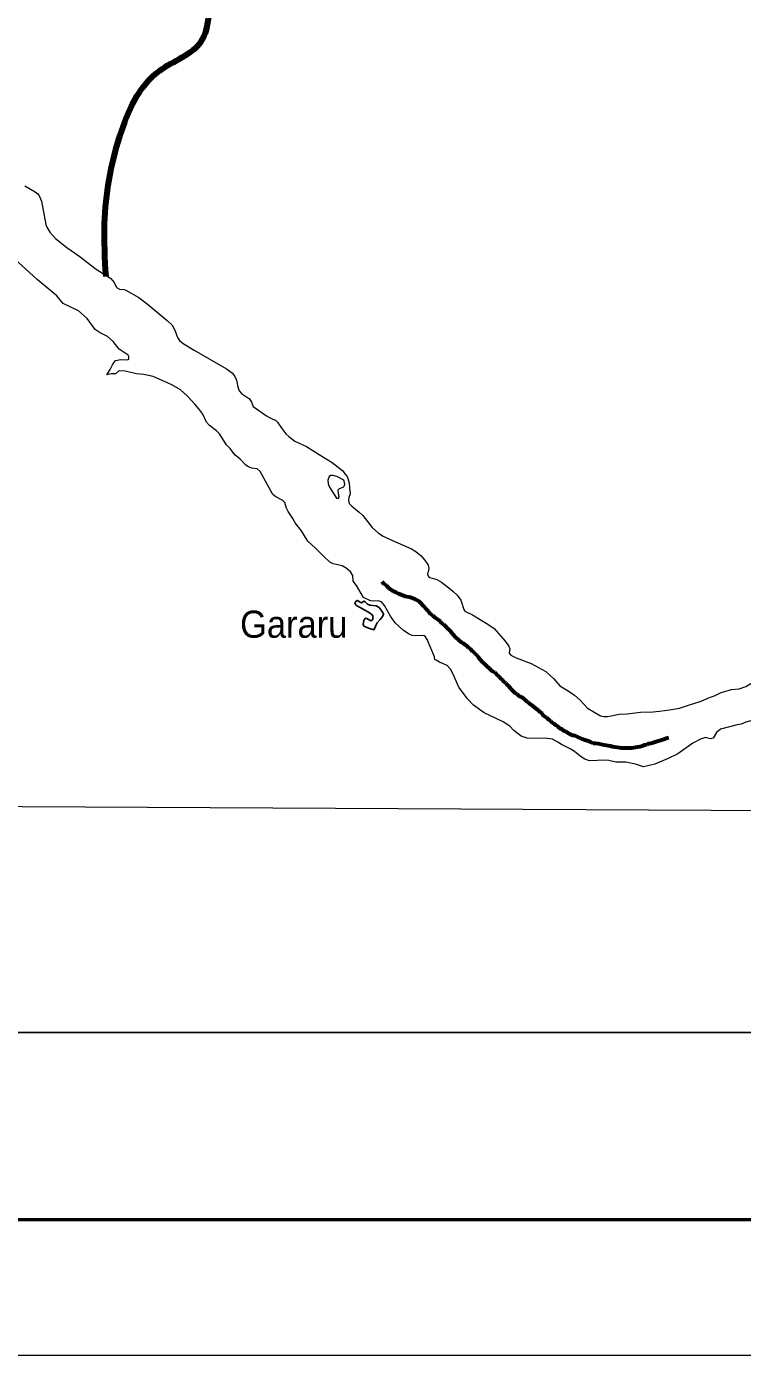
# Model space of a CAD drawing. Extents: x 553962 to 842807, y 8883888 to 9032388.
# Drawn here: x 703744 to 716936, y 8883888 to 8908376 of the extents above; entities that cross this region are included whole.
import ezdxf

# ---------------------------------------------------------------- set-up
doc = ezdxf.new("R2010")
doc.units = 0
doc.header["$LTSCALE"] = 150
doc.linetypes.add('LONG_DASH_SHORT_DASH', pattern=[9.9, 6, -1.2, 1.5, -1.2])
for name, color, linetype, lineweight in [('1', 7, 'Continuous', 13), ('21', 7, 'Continuous', 25), ('25', 7, 'Continuous', 13), ('3', 7, 'Continuous', 13), ('7', 7, 'LONG_DASH_SHORT_DASH', 60), ('9', 7, 'Continuous', 90)]:
    doc.layers.add(name, color=color, linetype=linetype, lineweight=lineweight)
doc.layers.add('41', color=7, linetype='Continuous')

msp = doc.modelspace()

# ---------------------------------------------------------------- linework, layer by layer
at = {"layer": '1'}
msp.add_lwpolyline([(564751.7, 8894587.5), (664411.9, 8894209.9), (791388.5, 8893536.2)], dxfattribs=at)
at = {"layer": '21'}
msp.add_lwpolyline([(710323, 8897547.4), (710310.6, 8897510.9), (710262.7, 8897448.5), (710205.4, 8897388.1), (710179.6, 8897340.9), (710149.4, 8897265.1), (710140.8, 8897256.9), (710043.9, 8897288.4), (709961.7, 8897329.1), (709947.6, 8897363.1), (709961.6, 8897429.2), (709984.2, 8897470), (709989.6, 8897472.6), (710012.7, 8897467.5), (710090.3, 8897425.2), (710122.4, 8897447.6), (710126, 8897519.8), (710103.3, 8897545.3), (710035.6, 8897588.8), (709826.1, 8897706.4), (709795.6, 8897744), (709810.8, 8897781.5), (709838, 8897800.1), (709914.9, 8897754.6), (709934.2, 8897760.9), (709942.3, 8897776.2), (709957.1, 8897785.6), (709980.8, 8897774.5), (710029.3, 8897733.8), (710072, 8897710.7), (710184.3, 8897701.5), (710239.2, 8897671.8), (710278.2, 8897623.4), (710322, 8897552.2)], close=True, dxfattribs=at)
at = {"layer": '25'}
for points in [[(703708.6, 8905443.2), (703903.3, 8905333.4), (703950.4, 8905293.2), (703983.7, 8905242.4), (704017.5, 8905157.8), (704100.5, 8904727.4), (704116.7, 8904678.1), (704169.6, 8904585.4), (704276.9, 8904471.4), (704483.1, 8904302.2), (704709.8, 8904149.5), (705025.3, 8903904.5), (705294.1, 8903731.4), (705355.9, 8903661.9), (705397.8, 8903579.9), (705416.3, 8903559.4), (705456.6, 8903537.1), (705545.2, 8903528.8), (705574.6, 8903518.8), (705812.1, 8903380.7), (705964.1, 8903265.1), (706335.8, 8902958.3), (706429, 8902870.5), (706478.4, 8902782.6), (706522.3, 8902644.6), (706561.4, 8902592.6), (706627.5, 8902537.3), (706829.4, 8902410.4), (707426.7, 8902069.6), (707536.7, 8901989.7), (707580.8, 8901930.1), (707613.5, 8901857.8), (707638, 8901734), (707661.4, 8901666.3), (707707.1, 8901616.1), (707849, 8901513.6), (707889.3, 8901456.4), (707921.2, 8901374.1), (708164.6, 8901203.2), (708234, 8901164.4), (708282.6, 8901144)], [(704418.9, 8903273.5), (704303.8, 8903412.4), (703938.7, 8903713.3), (703520.5, 8904092.8)], [(705417, 8902230.5), (705468.7, 8902243.1), (705601.7, 8902236.3), (705626.1, 8902249.9), (705630.1, 8902294), (705613.1, 8902318.7), (705450.5, 8902433.4), (705338.6, 8902571.8), (705237.8, 8902662.7), (705098.5, 8902732.8), (705008.4, 8902794.2), (704859.8, 8902995.3), (704700.7, 8903136.3), (704418.9, 8903273.5)], [(705223.5, 8901956.6), (705285.9, 8902055.5), (705327.2, 8902145.4), (705340, 8902163.9), (705340, 8902163.9)], [(705340, 8902163.9), (705380.2, 8902221.5), (705417, 8902230.5)], [(706917, 8901328.8), (706845.7, 8901419), (706706.3, 8901570.6), (706577.5, 8901683.7), (706418, 8901776), (706077.6, 8901924.8), (705902.1, 8901964.8), (705769.4, 8901975.3), (705559.8, 8902024.1), (705462.6, 8902034.1), (705436.9, 8902022.7), (705383.9, 8901976.1), (705305.7, 8901975.9), (705223.5, 8901956.6)], [(708884.8, 8898960.2), (708812.9, 8899081.1), (708692, 8899230.3), (708649.9, 8899313.3), (708562.2, 8899440.2), (708534.2, 8899502.9), (708503.8, 8899608.4), (708465.9, 8899644.1), (708336.8, 8899710.3), (708284.4, 8899750.1), (708047.8, 8900175.7), (707990.8, 8900226.5), (707897.1, 8900236.8), (707831, 8900260), (707784.3, 8900295.7), (707679.2, 8900403.7), (707579.3, 8900485.4), (707498.4, 8900600.3), (707426.9, 8900668.2), (707296.2, 8900870.2), (707244.9, 8900923.6), (707114.9, 8901025.9), (707060.8, 8901088.8), (706991.1, 8901234.8), (706917, 8901328.8)], [(708282.6, 8901144), (708331.2, 8901123.5), (708369.6, 8901088.6), (708444.9, 8900971.6), (708520.8, 8900871.2), (708577.2, 8900819.4), (708690.2, 8900735.5), (708901.9, 8900638.8), (709137.2, 8900490.7)], [(709137.2, 8900490.7), (709372.6, 8900342.6), (709571.9, 8900187.3), (709610.7, 8900136.5)], [(709610.7, 8900136.5), (709649.5, 8900085.8), (709687.8, 8899966.6), (709696.9, 8899867.4)], [(709696.9, 8899867.4), (709706, 8899768.3), (709680, 8899695), (709673.6, 8899642.5), (709691.5, 8899588), (709738.8, 8899535.9), (709875.6, 8899429.5), (709875.6, 8899429.5), (709939.8, 8899367.7), (710112.9, 8899145), (710229.9, 8899043.2), (710316.3, 8898983), (710434.5, 8898930.1)], [(709950.2, 8897853.8), (709826.5, 8898078.7), (709765, 8898154.3), (709755.6, 8898257.5), (709714.4, 8898328.8), (709634.6, 8898396.5), (709559.8, 8898439.4), (709395, 8898473.4), (709333.8, 8898506.8), (709214.9, 8898614.3), (709070.8, 8898765.5), (708925, 8898892.5), (708884.8, 8898960.2)], [(710434.5, 8898930.1), (710835, 8898750.5), (710918.4, 8898699.6), (711013.8, 8898623.8), (711070, 8898553.2)], [(711070, 8898553.2), (711126.2, 8898482.6), (711144.3, 8898448), (711158.3, 8898389.2), (711130.3, 8898282.3), (711152.8, 8898240), (711175.8, 8898222.2), (711302.1, 8898183.8), (711391.3, 8898138.3), (711554.3, 8898011), (711603.7, 8897966)], [(710692.4, 8897249.1), (710533.9, 8897388.5), (710451.3, 8897511.8), (710342.9, 8897708), (710286.4, 8897777.2), (710220.4, 8897794.9), (710145.3, 8897789.3), (710079.5, 8897794.7), (709950.2, 8897853.8)], [(711603.7, 8897966), (711680.2, 8897896.3), (711746, 8897808.5), (711799.4, 8897633.4), (711822.1, 8897601.2), (711960, 8897533.9), (712103.8, 8897448.7)], [(711124.5, 8897078.8), (711093, 8897127.9), (711068.7, 8897147.8), (711049.5, 8897152.8), (710908.8, 8897146.9), (710849.4, 8897155.7), (710797.6, 8897180.7), (710692.4, 8897249.1)], [(712103.8, 8897448.7), (712242.6, 8897366.3), (712359.3, 8897283.4), (712565.7, 8897048.4), (712631.8, 8896958.1), (712647.9, 8896909.4), (712637.9, 8896831.9), (712665.2, 8896790.9), (712768.3, 8896741.4), (713044.9, 8896638.8), (713311.2, 8896489.3), (713385.5, 8896424.1)], [(712525.7, 8895564.3), (712179.3, 8895726.8), (711977.5, 8895873.7), (711872.3, 8895986), (711707.5, 8896200.3), (711600.3, 8896454.3), (711553.8, 8896536.9), (711494.9, 8896598.8), (711354.3, 8896661.8), (711292.1, 8896701.3), (711270.5, 8896704.9), (711261.3, 8896763.5), (711124.5, 8897078.8)], [(716671.9, 8896141.4), (716736, 8896160), (716876.8, 8896172.9), (716996.8, 8896216.3), (717443.2, 8896481.3), (717658.9, 8896651.8), (717833.2, 8896772.8), (717934, 8896865.6), (718070.7, 8896913.8), (718220.3, 8896913.8), (718619, 8896913.8), (718918.1, 8896963.6), (719252.2, 8897020.3)], [(713385.5, 8896424.1), (713459.8, 8896359), (713569.8, 8896225.6), (713696.9, 8896155.1), (713818.3, 8896075.1), (713842, 8896053.8)], [(713842, 8896053.8), (713946.1, 8895960.1), (714080.1, 8895815.7), (714321.1, 8895672.2), (714384.5, 8895659.7), (714451.9, 8895662.4), (714514.6, 8895674.6)], [(715944.9, 8895871), (716177.3, 8895944.3), (716297, 8895998.6), (716434.9, 8896046.3), (716544.4, 8896104.3), (716671.9, 8896141.4)], [(715407.8, 8895761.9), (715591.5, 8895783.2), (715777.5, 8895818.2), (715944.9, 8895871)], [(719242.1, 8895974.6), (719137.8, 8895926.7), (719051.9, 8895910.8), (718819, 8895950.7), (718570.6, 8895982.3), (718406.7, 8895992.1), (718284.1, 8895976.8), (718038.4, 8895905.8), (717250.7, 8895623.3), (716998.4, 8895554.6), (716915, 8895518.1), (716881.8, 8895513.8)], [(713532.7, 8895186.2), (713435.1, 8895242.8), (713335.4, 8895258.7), (712968.6, 8895262), (712859.7, 8895301.9), (712725.3, 8895401.6), (712648.5, 8895483.1), (712525.7, 8895564.3)], [(714514.6, 8895674.6), (714664.7, 8895703.8), (714810.4, 8895708.8), (715055.3, 8895739.1), (715289.1, 8895748.2), (715407.8, 8895761.9)], [(716881.8, 8895513.8), (716841.2, 8895508.6), (716533, 8895427), (716458.2, 8895365.9), (716394.5, 8895260), (716374.9, 8895256.9)], [(715039.1, 8894760), (714963.6, 8894786.5), (714790.6, 8894820), (714606.1, 8894818.8), (714473.2, 8894853.3), (714404.1, 8894859.6), (714116.9, 8894843.6), (714034.5, 8894876.8), (713967, 8894916.7), (713850.5, 8895013.2), (713789.1, 8895053.9), (713604, 8895144.8), (713532.7, 8895186.2)], [(716374.9, 8895256.9), (716350.2, 8895253.1), (716257.5, 8895274.6), (716162.3, 8895243), (716023.3, 8895172.8), (715744.1, 8894976.4), (715570.5, 8894886.6), (715322, 8894784.1), (715114.6, 8894733.5), (715039.1, 8894760)]]:
    msp.add_lwpolyline(points, dxfattribs=at)
msp.add_lwpolyline([(709580.3, 8899889.8), (709596.2, 8899906.3), (709606, 8899943.5), (709599.7, 8899997.3), (709588.6, 8900017.3), (709459.5, 8900083.7), (709393.7, 8900104.9), (709351.6, 8900105.7), (709323, 8900086.1), (709294.9, 8900014.3), (709301.9, 8899949.1), (709327.1, 8899890.5), (709454.5, 8899688.2), (709485.7, 8899677.3), (709503.8, 8899701.2), (709483.4, 8899821.2), (709487.6, 8899841.5), (709510.1, 8899860.5)], close=True, dxfattribs=at)
at = {"layer": '3'}
msp.add_lwpolyline([(842807.3, 9032387.8), (842807.3, 8883887.8), (553961.7, 8883887.8), (553961.7, 9032387.8)], close=True, dxfattribs=at)
at = {"layer": '3', "lineweight": 53}
msp.add_lwpolyline([(840307.3, 9029887.8), (840307.3, 8886387.8), (560211.7, 8886387.8), (560211.7, 9029887.8)], close=True, dxfattribs=at)
at = {"layer": '3', "lineweight": 25}
msp.add_lwpolyline([(563033.9, 9026438.8), (793061.1, 9026438.8), (793495.6, 8889836.8), (563468.3, 8889836.8)], close=True, dxfattribs=at)
at = {"layer": '7'}
for points in [[(711474.4, 8897314.1), (711433.6, 8897355), (711398, 8897378), (711370, 8897413.8), (711308.9, 8897454.7), (711270.7, 8897477.7), (711230, 8897521.1), (711189.3, 8897549.2), (711148.6, 8897600.3), (711112.9, 8897631), (711056.9, 8897694.9), (711016.2, 8897746.1), (710965.3, 8897792.1), (710911.8, 8897817.6), (710817.7, 8897856), (710718.5, 8897873.8), (710647.2, 8897904.5), (710598.8, 8897925), (710555.6, 8897945.4), (710507.2, 8897965.9), (710481.8, 8897986.3), (710448.7, 8898001.7), (710413.1, 8898034.9), (710374.9, 8898073.2), (710334.2, 8898098.8), (710296.3, 8898144.4)], [(712701.2, 8896140.8), (712675.8, 8896166.4), (712632.5, 8896220.1), (712599.4, 8896243.1), (712581.6, 8896276.3), (712546, 8896294.2), (712525.6, 8896327.4), (712487.4, 8896347.9), (712467.1, 8896388.8), (712431.4, 8896414.3), (712375.4, 8896475.7), (712327.1, 8896498.7), (712276.2, 8896547.2), (712230.3, 8896585.6), (712176.9, 8896636.7), (712146.3, 8896664.8), (712110.7, 8896708.3), (712075.1, 8896746.6), (712052.2, 8896784.9), (712016.5, 8896805.4), (711996.2, 8896843.7), (711960.5, 8896861.6), (711924.9, 8896910.2), (711889.3, 8896928.1), (711866.3, 8896958.8), (711830.7, 8896976.7), (711795.1, 8897009.9), (711759.5, 8897027.8), (711718.7, 8897061), (711695.8, 8897081.5), (711657.6, 8897112.1), (711619.5, 8897158.2), (711594, 8897186.3), (711555.8, 8897232.3), (711532.9, 8897257.8), (711497.3, 8897291.1), (711474.4, 8897314.1)], [(715172.3, 8895138.8), (715134.1, 8895136.3), (715085.8, 8895115.8), (715047.6, 8895103.1), (715004.4, 8895095.4), (714963.7, 8895087.7), (714935.7, 8895082.6), (714900.1, 8895077.5), (714841.5, 8895077.5), (714803.3, 8895077.5), (714762.7, 8895077.5), (714739.7, 8895077.5), (714701.6, 8895080), (714673.6, 8895082.6), (714625.2, 8895090.3), (714582, 8895097.9), (714541.3, 8895105.6), (714503.1, 8895113.3), (714464.9, 8895120.9), (714431.8, 8895128.6), (714391.1, 8895136.3), (714332.6, 8895143.9), (714279.2, 8895159.3), (714230.8, 8895166.9), (714185, 8895166.9), (714144.3, 8895187.4), (714096, 8895205.3), (714055.2, 8895220.6), (714034.9, 8895225.7), (714004.3, 8895241.1), (713984, 8895246.2), (713945.8, 8895264.1), (713922.9, 8895269.2), (713889.8, 8895289.6), (713851.6, 8895307.5), (713808.4, 8895310.1), (713762.6, 8895328), (713732, 8895345.9), (713693.9, 8895376.5), (713653.1, 8895391.9), (713612.4, 8895425.1), (713569.2, 8895440.4), (713541.2, 8895471.1), (713503, 8895496.7), (713467.3, 8895527.3), (713429.2, 8895547.8), (713403.7, 8895581), (713370.6, 8895601.5), (713324.8, 8895642.4), (713273.9, 8895670.5), (713248.5, 8895716.5), (713210.3, 8895739.5), (713177.2, 8895775.3), (713131.4, 8895811.1), (713098.3, 8895831.5), (713057.6, 8895869.9), (713032.1, 8895885.2), (712991.4, 8895918.4), (712968.5, 8895933.8), (712930.3, 8895972.1), (712871.8, 8896020.7), (712828.5, 8896033.5), (712787.8, 8896074.3), (712747.1, 8896094.8), (712701.2, 8896140.8)], [(715575.1, 8895269.4), (715574.3, 8895269.2), (715533.6, 8895253.9), (715487.8, 8895238.5), (715444.5, 8895225.8), (715347.8, 8895195.1), (715294.4, 8895177.2), (715248.6, 8895164.4), (715200.3, 8895159.3), (715172.3, 8895138.8)]]:
    msp.add_lwpolyline(points, dxfattribs=at)
at = {"layer": '9'}
msp.add_spline([(705207.9, 8903769.6), (705180.7, 8904747.4), (705463.8, 8906360), (706198.7, 8907564.6), (706955.5, 8908091.1), (707178.8, 8909156.3), (707379.5, 8909664.2), (707580.3, 8910146.8), (707959.3, 8910554.8), (708516.4, 8910888.1), (708891.3, 8912131.7), (709193.2, 8912716.3), (709242.2, 8913071.2)], degree=3, dxfattribs=at)

# ---------------------------------------------------------------- texts
at = {"layer": '41', "width": 0.95}
msp.add_text('Gararu', height=500, dxfattribs=at).set_placement((707678.8, 8897112.8))

doc.saveas('drawing.dxf')
